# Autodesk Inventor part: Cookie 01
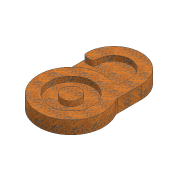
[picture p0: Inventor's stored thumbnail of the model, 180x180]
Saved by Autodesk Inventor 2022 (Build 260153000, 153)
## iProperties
RuleStatus: InUse
Created: 2022-09
Part Number: Cookie 01
Material: Generic
Document SubType Name: Modeling
Designer: Lance
Mass: 26.4461 g
Surface Area: 93.5409 cm^2
Volume: 26.4461 cm^3
Density: 1 g/cm^3
Sheet Metal Rule: Default_mm
Appearance: Rust
BeforeDocSave0: MATERIAL DETAILS
BeforeDocSave1: ! iProps Material Part Number
BeforeDocSave2: CUSTOM iPROPS RULE
AfterDocNew0: IdentifyFiletype
AfterDocNew1: THICKNESS ENTRY
THICKNESS: 0.0
MASS: 0.0
ROLLING INSIDE RADIUS: 0.0
ROLLING OUTSIDE RADIUS: 0.0
OD: 0.0
ID: 0.0
ROLLINGLENGTH: 0.0
Author: Lance
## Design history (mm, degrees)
sketch "Sketch1"
  geometry: L1 (-21.25, -33)-(-21.25, -13.17); L2 (21.25, -33)-(21.25, -13.17); L3 (12.75, -30)-(21.25, -30); L4 (12.75, -33)-(12.75, -30); L5 (-12.75, -33)-(-12.75, -21.504); C1 r 16.5 at (0, 0); C2 r 7 at (0, 0); A1 r 25 centre (0, 0) between (-12.75, -21.504) and (-21.25, -13.17); A2 r 21.25 centre (0, -33) between (-21.25, -33) and (21.25, -33); A3 r 12.75 centre (0, -33) between (-12.75, -33) and (12.75, -33); 1 further point
  constraints: 10 end point, 7 point on circle, 5 centre point, 4 tangent, 3 parallel, 1 coincident, 1 perpendicular, 1 point on line, 1 vertical, 1 vertical alignment
  dimensions: "d0" = 50 diameter of A1; "d1" = 42.5 diameter of A2; "d2" = 33 diameter of C1 (derived); "d3" = 14 diameter of C2; "d4" = 33 distance of C1.centre A2.centre; "d5" = 3 distance from line of A2.centre L3; "d6" = 8.5 distance between parallel lines of L2 L4; "d7" = 8.5 radial gap between concentric circles of C1 A1
extrude "Extrusion1" new body sketch "Sketch1" distance "d8" = 10; taper "d9" = 0 deg
extrude "Extrusion2" join sketch "Sketch1" distance "d10" = 6; taper "d11" = 0 deg
fillet "Fillet3" dims "d14" = 3
fillet "Fillet4" dims "d15" = 6
body "Solid1"
other parameters: "Thickness" = 5, "BendRadius" = 5 (= Thickness), "BendReliefWidth" = 5 (= Thickness), "BendReliefDepth" = 2.5 (= 0.5 x Thickness), "SeamGap" = 0.01, "TransitionRadius" = 5 (= BendRadius), "JacobiRadiusSize" = 5 (= BendRadius), "GapSize" = 5 (= Thickness), "Length" = 0 [user parameter], "Width" = 0 [user parameter], "Height" = 0 [user parameter], "Thick" = 0 [user parameter], "OD" = 0 [user parameter], "ID" = 0 [user parameter], "Wall" = 0 [user parameter], "Lip" = 0 [user parameter], "MassPerMetre" = 0 [user parameter], "FlatLength" = 0 [user parameter], "FlatWidth" = 0 [user parameter], "FlatThick" = 0 [user parameter], "FlatLong" = 0 [user parameter], "FlatShort" = 0 [user parameter], "ExtentsLong" = 0 [user parameter], "ExtentsMed" = 0 [user parameter], "ExtentsShort" = 0 [user parameter], "RollingOD" = 0 [user parameter], "RollingID" = 0 [user parameter], "RollingOutsideRadius" = 0 [user parameter], "RollingInsideRadius" = 0 [user parameter], "RollingWall" = 0 [user parameter], "RollingLength" = 0 [user parameter]
